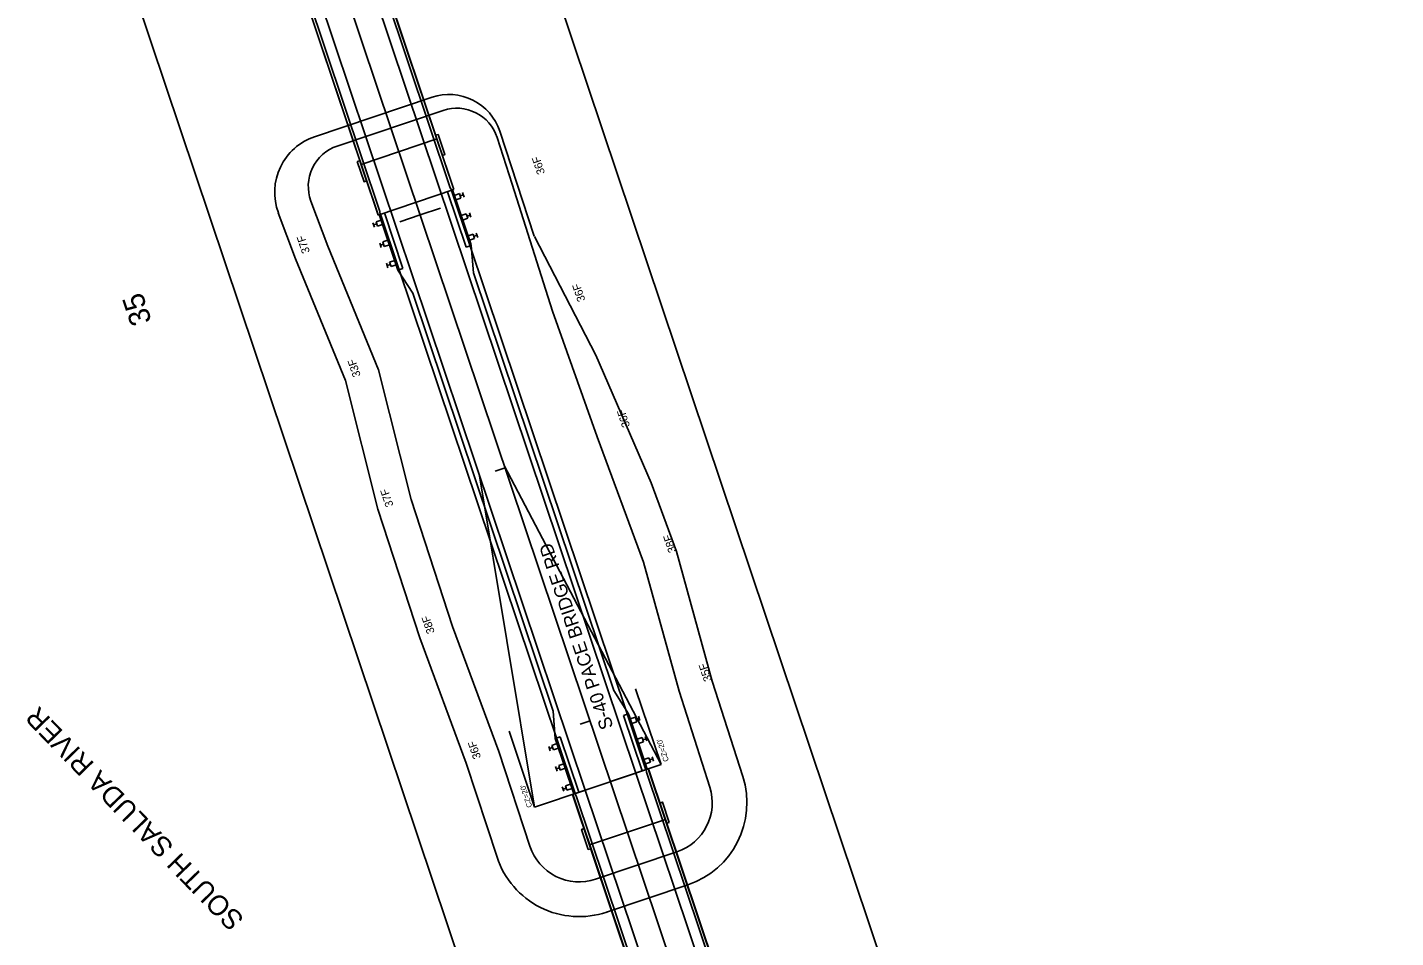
# Model space of a CAD drawing. Extents: x 1528853 to 1624411, y 1119753 to 1162242.
# Drawn here: x 1529401 to 1529913, y 1160305 to 1160646 of the extents above; entities that cross this region are included whole.
import ezdxf

# ---------------------------------------------------------------- set-up
doc = ezdxf.new("R2010")
doc.units = 0
for name, color, linetype in [('BR_CONCRETE', 7, 'Continuous'), ('BR_PROPOSED_TRAVELWAY', 7, 'Continuous'), ('RD_EX_Road Text', 7, 'Continuous'), ('RD_HC_Cl', 7, 'Continuous'), ('RD_HC_Data', 7, 'Continuous'), ('RD_HC_Data_Tic', 7, 'Continuous'), ('RD_HC_TX_Sta50', 7, 'Continuous'), ('RD_PD_BOC', 7, 'Continuous'), ('RD_PD_CstnLmt', 7, 'Continuous'), ('RD_PD_CstnLmt_TX', 7, 'Continuous'), ('RD_PD_DR_ErosCtrl', 7, 'Continuous'), ('RD_PD_Final_TrvlWay', 7, 'Continuous'), ('RD_PD_GR', 7, 'Continuous'), ('RD_PD_PaveShd', 7, 'Continuous'), ('RD_PD_RW', 7, 'Continuous'), ('RD_Sketch8', 7, 'Continuous')]:
    doc.layers.add(name, color=color, linetype=linetype)

# ---------------------------------------------------------------- blocks, each defined once
blk = doc.blocks.new('Guardrail_MTBBC2_Transition')
at = {"layer": 'RD_PD_GR'}
for p, q in [((0, 0.5), (0, 0)), ((21.25, 0.5), (0, 0.5)), ((0, 0), (21.25, 0)), ((3.875, 3.75), (2.125, 3.75)), ((2.125, 0.5), (2.125, 2.5)), ((2.125, 2.5), (3.875, 2.5)), ((3.875, 0.5), (2.125, 0.5)), ((3, 2.5), (3, 3.75)), ((3.875, 2.5), (3.875, 0.5)), ((11.875, 3.75), (10.125, 3.75)), ((10.125, 0.5), (10.125, 2.5)), ((10.125, 2.5), (11.875, 2.5)), ((11.875, 0.5), (10.125, 0.5)), ((11, 2.5), (11, 3.75)), ((11.875, 2.5), (11.875, 0.5)), ((15, 0.5), (15, 0)), ((19.875, 3.75), (18.125, 3.75)), ((18.125, 0.5), (18.125, 2.5)), ((18.125, 2.5), (19.875, 2.5)), ((19.875, 0.5), (18.125, 0.5)), ((19, 2.5), (19, 3.75)), ((19.875, 2.5), (19.875, 0.5)), ((21.25, 0), (21.25, 0.5))]:
    blk.add_line(p, q, dxfattribs=at)

msp = doc.modelspace()

# ---------------------------------------------------------------- linework, layer by layer
at = {"layer": 'BR_CONCRETE'}
for p, q in [((1529560.43, 1160585.64), (1529522.22, 1160699.39)), ((1529560.51, 1160585.66), (1529522.3, 1160699.42)), ((1529559.16, 1160586.27), (1529521.59, 1160698.13)), ((1529532.07, 1160576.11), (1529493.86, 1160689.87)), ((1529532.15, 1160576.14), (1529493.94, 1160689.89)), ((1529532.78, 1160577.4), (1529495.2, 1160689.26)), ((1529525.7, 1160595.07), (1529554.14, 1160604.62)), ((1529532.07, 1160576.11), (1529560.51, 1160585.66)), ((1529559.16, 1160586.27), (1529559.72, 1160585.4)), ((1529532.78, 1160577.4), (1529532.86, 1160576.38)), ((1529633.43, 1160368.58), (1529604.99, 1160359.03)), ((1529632.72, 1160367.29), (1529632.64, 1160368.32)), ((1529692.58, 1160189.08), (1529632.72, 1160367.29)), ((1529693.85, 1160188.45), (1529633.35, 1160368.56)), ((1529693.93, 1160188.48), (1529633.43, 1160368.58)), ((1529604.99, 1160359.03), (1529665.49, 1160178.92)), ((1529665.57, 1160178.95), (1529605.07, 1160359.06)), ((1529606.34, 1160358.43), (1529605.78, 1160359.3)), ((1529666.2, 1160180.22), (1529606.34, 1160358.43)), ((1529611.36, 1160340.07), (1529639.8, 1160349.63))]:
    msp.add_line(p, q, dxfattribs=at)
for points in [[(1529554.61, 1160606.36), (1529553.66, 1160606.05), (1529556.21, 1160598.46), (1529557.16, 1160598.78)], [(1529524.28, 1160596.17), (1529525.22, 1160596.49), (1529527.77, 1160588.91), (1529526.82, 1160588.59)], [(1529641.22, 1160348.52), (1529640.27, 1160348.2), (1529637.73, 1160355.79), (1529638.68, 1160356.11)], [(1529610.89, 1160338.33), (1529611.84, 1160338.65), (1529609.29, 1160346.23), (1529608.34, 1160345.92)]]:
    msp.add_lwpolyline(points, close=True, dxfattribs=at)
at = {"layer": 'BR_PROPOSED_TRAVELWAY'}
for p, q in [((1529689.19, 1160186.88), (1529628.69, 1160366.99)), ((1529670.23, 1160180.51), (1529609.73, 1160360.62))]:
    msp.add_line(p, q, dxfattribs=at)
at = {"layer": 'RD_HC_Cl'}
msp.add_line((1529913.5, 1159487.74), (1529500.12, 1160718.34), dxfattribs=at)
at = {"layer": 'RD_HC_Data_Tic'}
for p, q in [((1529547.88, 1160576.15), (1529540.3, 1160573.6)), ((1529547.88, 1160576.15), (1529555.46, 1160578.7)), ((1529579.72, 1160481.35), (1529575.93, 1160480.08)), ((1529611.57, 1160386.56), (1529607.78, 1160385.29))]:
    msp.add_line(p, q, dxfattribs=at)
at = {"layer": 'RD_PD_BOC'}
for p, q in [((1529558.14, 1160584.87), (1529565.12, 1160564.09)), ((1529560.03, 1160585.51), (1529567.01, 1160564.73)), ((1529532.54, 1160576.27), (1529539.52, 1160555.5)), ((1529534.44, 1160576.91), (1529541.42, 1160556.13)), ((1529565.12, 1160564.09), (1529567.01, 1160564.73)), ((1529541.42, 1160556.13), (1529539.52, 1160555.5)), ((1529624.08, 1160388.56), (1529625.98, 1160389.2)), ((1529631.06, 1160367.79), (1529624.08, 1160388.56)), ((1529632.95, 1160368.43), (1529625.98, 1160389.2)), ((1529600.38, 1160380.6), (1529598.49, 1160379.97)), ((1529607.36, 1160359.83), (1529600.38, 1160380.6)), ((1529605.46, 1160359.19), (1529598.49, 1160379.97))]:
    msp.add_line(p, q, dxfattribs=at)
at = {"layer": 'RD_PD_CstnLmt'}
for p, q in [((1529556.54, 1160615.34), (1529516.76, 1160601.98)), ((1529582.39, 1160587.74), (1529576.72, 1160605.19)), ((1529597.52, 1160540.08), (1529582.39, 1160587.74)), ((1529513.21, 1160564.5), (1529506.93, 1160581.35)), ((1529532.28, 1160518.16), (1529513.21, 1160564.5)), ((1529614.25, 1160492.95), (1529597.52, 1160540.08)), ((1529544.54, 1160469.53), (1529532.28, 1160518.16)), ((1529631.62, 1160446.04), (1529614.25, 1160492.95)), ((1529560.01, 1160421.99), (1529544.54, 1160469.53)), ((1529644.9, 1160397.76), (1529631.62, 1160446.04)), ((1529577.35, 1160375.07), (1529560.01, 1160421.99)), ((1529656.41, 1160361.76), (1529644.9, 1160397.76)), ((1529589.03, 1160339.56), (1529577.35, 1160375.07)), ((1529644.11, 1160337.47), (1529613.64, 1160327.23))]:
    msp.add_line(p, q, dxfattribs=at)
for centre, radius, start, end in [((1529561.6, 1160600.27), 15.89, 18.0045, 108.568), ((1529521.82, 1160586.91), 15.89, 108.568, 200.461), ((1529637.94, 1160355.86), 19.4, 288.568, 17.7299), ((1529607.46, 1160345.62), 19.4, 198.2124, 288.568)]:
    msp.add_arc(centre, radius, start, end, dxfattribs=at)
at = {"layer": 'RD_PD_DR_ErosCtrl'}
for p, q in [((1529552.31, 1160620.25), (1529508.31, 1160605.47)), ((1529590.64, 1160568.16), (1529577.67, 1160607.54)), ((1529501.11, 1160559.76), (1529494.7, 1160576.92)), ((1529613.7, 1160523.59), (1529590.7, 1160568.02)), ((1529519.9, 1160514.08), (1529501.11, 1160559.76)), ((1529634.46, 1160475.8), (1529613.67, 1160523.65)), ((1529532.04, 1160465.93), (1529519.9, 1160514.08)), ((1529644.01, 1160450.03), (1529634.46, 1160475.8)), ((1529547.73, 1160417.72), (1529532.04, 1160465.93)), ((1529657.37, 1160401.46), (1529644.01, 1160450.03)), ((1529565.08, 1160370.78), (1529547.73, 1160417.72)), ((1529668.79, 1160365.72), (1529657.37, 1160401.46)), ((1529576.69, 1160335.49), (1529565.08, 1160370.78)), ((1529648.25, 1160325.15), (1529617.77, 1160314.91))]:
    msp.add_line(p, q, dxfattribs=at)
for centre, radius, start, end in [((1529558.68, 1160601.29), 20, 18.2254, 108.568), ((1529515.32, 1160584.61), 22, 108.568, 200.461), ((1529637.94, 1160355.86), 32.4, 288.568, 17.7299), ((1529607.46, 1160345.62), 32.4, 198.2124, 288.568)]:
    msp.add_arc(centre, radius, start, end, dxfattribs=at)
at = {"layer": 'RD_PD_Final_TrvlWay'}
for p, q in [((1529628.69, 1160366.99), (1529509.6, 1160721.52)), ((1529609.73, 1160360.62), (1529490.64, 1160715.16))]:
    msp.add_line(p, q, dxfattribs=at)
at = {"layer": 'RD_PD_GR'}
for p, q in [((1529566.33, 1160565.2), (1529625.71, 1160388.41)), ((1529599.17, 1160379.49), (1529539.78, 1160556.29))]:
    msp.add_line(p, q, dxfattribs=at)
at = {"layer": 'RD_PD_PaveShd'}
for p, q in [((1529567.01, 1160564.73), (1529567.82, 1160554.47)), ((1529539.52, 1160555.5), (1529545.08, 1160546.8)), ((1529620.42, 1160397.9), (1529567.82, 1160554.47)), ((1529597.67, 1160390.23), (1529545.08, 1160546.8)), ((1529625.98, 1160389.2), (1529620.42, 1160397.9)), ((1529598.49, 1160379.97), (1529597.67, 1160390.23))]:
    msp.add_line(p, q, dxfattribs=at)
at = {"layer": 'RD_PD_RW'}
for p, q in [((1529881.68, 1159817.98), (1529571.21, 1160742.22)), ((1529715.61, 1159841.31), (1529429.02, 1160694.46))]:
    msp.add_line(p, q, dxfattribs=at)
at = {"layer": 'RD_Sketch8'}
for p, q in [((1529590.77, 1160354.26), (1529569.93, 1160479.12)), ((1529638.17, 1160370.18), (1529579.41, 1160482.3)), ((1529638.17, 1160370.18), (1529628.62, 1160398.62)), ((1529590.77, 1160354.26), (1529581.22, 1160382.69)), ((1529619.21, 1160363.81), (1529638.17, 1160370.18)), ((1529609.73, 1160360.62), (1529590.77, 1160354.26))]:
    msp.add_line(p, q, dxfattribs=at)

# ---------------------------------------------------------------- block references
at = {"layer": 'RD_PD_BOC'}
for p, rotation in [((1529559.56, 1160585.35), -71.4319942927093), ((1529605.94, 1160359.35), 108.5680057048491)]:
    msp.add_blockref('Guardrail_MTBBC2_Transition', p, dxfattribs=dict(at, rotation=rotation))
for p, yscale, rotation in [((1529533.02, 1160576.43), -0.9999999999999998, -71.43199429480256), ((1529632.48, 1160368.27), -0.9999999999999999, 108.56800570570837)]:
    msp.add_blockref('Guardrail_MTBBC2_Transition', p, dxfattribs=dict(at, yscale=yscale, rotation=rotation))

# ---------------------------------------------------------------- texts
at = {"layer": 'RD_EX_Road Text'}
msp.add_text('S-40 PACE BRIDGE RD', height=5, rotation=108.5527, dxfattribs=at).set_placement((1529620.35, 1160384.32))
at = {"layer": 'RD_HC_Data'}
msp.add_text('SOUTH SALUDA RIVER', height=7.5, rotation=134.1026, dxfattribs=at).set_placement((1529482.26, 1160312.47))
at = {"layer": 'RD_HC_TX_Sta50'}
msp.add_text('35', height=8, rotation=108.568, dxfattribs=at).set_placement((1529447.34, 1160536.3))
at = {"layer": 'RD_PD_CstnLmt_TX'}
for s, p in [('36F', (1529594.71, 1160591.88)), ('37F', (1529506.58, 1160562.27)), ('36F', (1529609.84, 1160544.22)), ('33F', (1529525.64, 1160515.93)), ('36F', (1529626.57, 1160497.09)), ('37F', (1529537.9, 1160467.3)), ('38F', (1529643.94, 1160450.18)), ('38F', (1529553.37, 1160419.76)), ('35F', (1529657.23, 1160401.9)), ('36F', (1529570.72, 1160372.84))]:
    msp.add_text(s, height=3, rotation=108.568, dxfattribs=at).set_placement(p)
at = {"layer": 'RD_Sketch8'}
for p in [(1529641.12, 1160371.64), (1529589.89, 1160354.43)]:
    msp.add_text("CZ=20'", height=2, rotation=108.3453, dxfattribs=at).set_placement(p)

doc.saveas('drawing.dxf')
